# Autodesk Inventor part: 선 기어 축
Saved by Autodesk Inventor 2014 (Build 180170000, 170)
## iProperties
Created: 2026-05
Part Number: 선 기어 축
Material: 일반
Document SubType Name: Modeling
Designer: dg
Density: 1 g/cm^3
Appearance: 기본값
Author: dg
Author: jhkim
Creation Date: 2026-04-27
Sending System: Autodesk Inventor 2027
Preprocessor: ST-DEVELOPER v20.1
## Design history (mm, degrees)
node "선 기어 축1"
node "솔리드1"
node "기준1"
